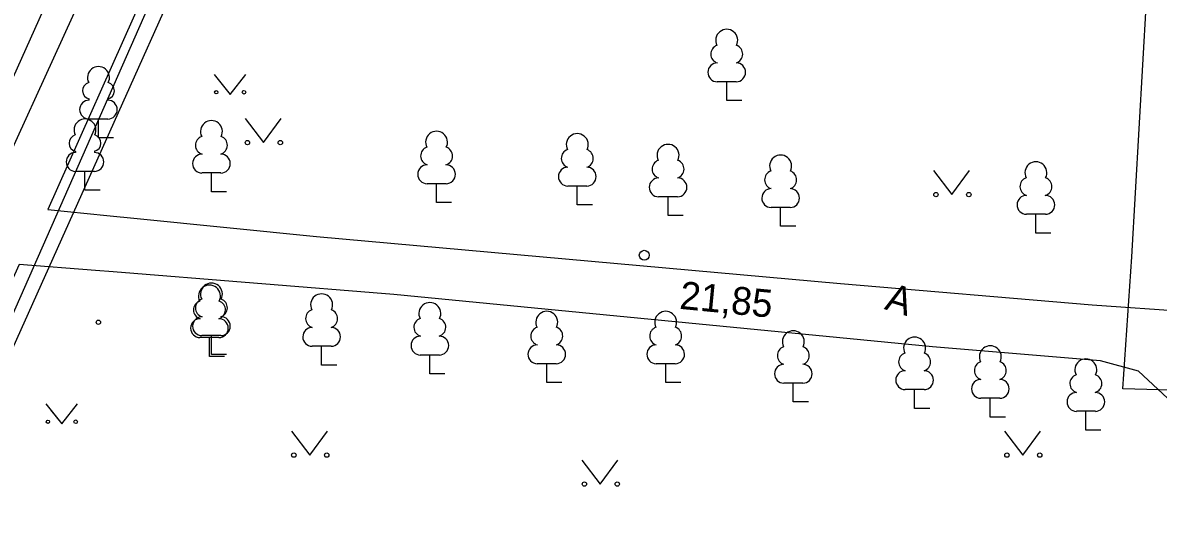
# Model space of a CAD drawing. Extents: x 714391 to 714584, y 6589993 to 6590151.
# Drawn here: x 714428.09 to 714456.74, y 6590018.98 to 6590031.55 of the extents above; entities that cross this region are included whole.
import ezdxf

# ---------------------------------------------------------------- set-up
doc = ezdxf.new("R2010")
doc.units = 0
for name, color, linetype in [('HALJASTUS', 7, 'Continuous'), ('HOONE', 7, 'Continuous'), ('KORGUS', 7, 'Continuous'), ('KPKAABEL', 7, 'Continuous'), ('PUU', 7, 'Continuous'), ('TEE', 7, 'Continuous'), ('По умолчанию', 7, 'Continuous'), ('Слой 1', 7, 'Continuous')]:
    doc.layers.add(name, color=color, linetype=linetype)

msp = doc.modelspace()

# ---------------------------------------------------------------- linework, layer by layer
at = {"layer": 'HALJASTUS'}
for p, q in [((714432.919, 6590030.25), (714433.324, 6590029.745)), ((714433.324, 6590029.745), (714433.719, 6590030.25)), ((714433.697, 6590029.137), (714434.16, 6590028.53)), ((714434.16, 6590028.53), (714434.606, 6590029.137)), ((714451.067, 6590027.827), (714451.53, 6590027.22)), ((714451.53, 6590027.22), (714451.976, 6590027.827)), ((714428.674, 6590021.941), (714429.079, 6590021.436)), ((714428.792, 6590021.794), (714429.079, 6590021.436)), ((714429.079, 6590021.436), (714429.474, 6590021.941)), ((714429.079, 6590021.436), (714429.474, 6590021.941)), ((714434.867, 6590021.257), (714435.33, 6590020.65)), ((714435.33, 6590020.65), (714435.776, 6590021.257)), ((714452.857, 6590021.257), (714453.32, 6590020.65)), ((714453.32, 6590020.65), (714453.766, 6590021.257)), ((714442.197, 6590020.527), (714442.66, 6590019.92)), ((714442.66, 6590019.92), (714443.106, 6590020.527))]:
    msp.add_line(p, q, dxfattribs=at)
for centre, radius in [((714432.971, 6590029.8), 0.0428), ((714433.671, 6590029.8), 0.0452), ((714433.759, 6590028.53), 0.055), ((714434.588, 6590028.53), 0.055), ((714451.129, 6590027.22), 0.055), ((714451.958, 6590027.22), 0.055), ((714428.726, 6590021.492), 0.0428), ((714428.726, 6590021.492), 0.0428), ((714429.426, 6590021.492), 0.0452), ((714429.426, 6590021.492), 0.0452), ((714434.929, 6590020.65), 0.055), ((714435.758, 6590020.65), 0.055), ((714452.919, 6590020.65), 0.055), ((714453.748, 6590020.65), 0.055), ((714442.259, 6590019.92), 0.055), ((714443.088, 6590019.92), 0.055)]:
    msp.add_circle(centre, radius, dxfattribs=at)
at = {"layer": 'HOONE'}
for points in [[(714459.73, 6590096.05), (714450.33, 6590074.44), (714440.46, 6590052.39), (714432.7, 6590035.24), (714421.56, 6590009.98), (714417.1, 6590000.12), (714413.783, 6589992.711)], [(714458.89, 6590022.24), (714455.84, 6590022.32), (714456.07, 6590025.65), (714456.9, 6590040.18), (714456.96, 6590042.47)]]:
    msp.add_lwpolyline(points, dxfattribs=at)
at = {"layer": 'KORGUS'}
msp.add_circle((714443.77, 6590025.69), 0.125, dxfattribs=at)
at = {"layer": 'KPKAABEL'}
msp.add_lwpolyline([(714390.649, 6590090.709), (714391.22, 6590087.72), (714411.651, 6590078.699), (714417.543, 6590076.021), (714419.18, 6590075.27), (714445.64, 6590069.88), (714433.16, 6590042.04), (714420.76, 6590014.4), (714410.92, 6589992.711)], dxfattribs=at)
at = {"layer": 'PUU'}
for p, q in [((714446.09, 6590030.065), (714445.61, 6590030.065)), ((714445.85, 6590029.59), (714445.85, 6590030.065)), ((714429.76, 6590029.63), (714429.76, 6590029.6)), ((714430.24, 6590029.63), (714430.24, 6590029.6)), ((714446.23, 6590029.59), (714445.85, 6590029.59)), ((714430.24, 6590029.125), (714429.76, 6590029.125)), ((714430, 6590028.65), (714430, 6590029.125)), ((714430.38, 6590028.65), (714430, 6590028.65)), ((714429.42, 6590028.31), (714429.42, 6590028.28)), ((714429.9, 6590028.31), (714429.9, 6590028.28)), ((714429.9, 6590027.805), (714429.42, 6590027.805)), ((714429.66, 6590027.33), (714429.66, 6590027.805)), ((714433.09, 6590027.765), (714432.61, 6590027.765)), ((714432.85, 6590027.29), (714432.85, 6590027.765)), ((714430.04, 6590027.33), (714429.66, 6590027.33)), ((714433.23, 6590027.29), (714432.85, 6590027.29)), ((714438.77, 6590027.495), (714438.29, 6590027.495)), ((714438.53, 6590027.02), (714438.53, 6590027.495)), ((714442.32, 6590027.435), (714441.84, 6590027.435)), ((714442.08, 6590026.96), (714442.08, 6590027.435)), ((714438.91, 6590027.02), (714438.53, 6590027.02)), ((714442.46, 6590026.96), (714442.08, 6590026.96)), ((714444.61, 6590027.165), (714444.13, 6590027.165)), ((714444.37, 6590026.69), (714444.37, 6590027.165)), ((714444.75, 6590026.69), (714444.37, 6590026.69)), ((714447.45, 6590026.895), (714446.97, 6590026.895)), ((714447.21, 6590026.42), (714447.21, 6590026.895)), ((714453.89, 6590026.725), (714453.41, 6590026.725)), ((714453.65, 6590026.25), (714453.65, 6590026.725)), ((714447.59, 6590026.42), (714447.21, 6590026.42)), ((714454.03, 6590026.25), (714453.65, 6590026.25)), ((714433.04, 6590023.615), (714432.56, 6590023.615)), ((714433.09, 6590023.665), (714432.61, 6590023.665)), ((714432.8, 6590023.14), (714432.8, 6590023.615)), ((714432.85, 6590023.19), (714432.85, 6590023.665)), ((714435.87, 6590023.395), (714435.39, 6590023.395)), ((714435.63, 6590022.92), (714435.63, 6590023.395)), ((714433.18, 6590023.14), (714432.8, 6590023.14)), ((714433.23, 6590023.19), (714432.85, 6590023.19)), ((714438.6, 6590023.175), (714438.12, 6590023.175)), ((714438.36, 6590022.7), (714438.36, 6590023.175)), ((714441.55, 6590022.955), (714441.07, 6590022.955)), ((714441.31, 6590022.48), (714441.31, 6590022.955)), ((714444.55, 6590022.955), (714444.07, 6590022.955)), ((714444.31, 6590022.48), (714444.31, 6590022.955)), ((714436.01, 6590022.92), (714435.63, 6590022.92)), ((714438.74, 6590022.7), (714438.36, 6590022.7)), ((714441.69, 6590022.48), (714441.31, 6590022.48)), ((714444.69, 6590022.48), (714444.31, 6590022.48)), ((714447.77, 6590022.465), (714447.29, 6590022.465)), ((714447.53, 6590021.99), (714447.53, 6590022.465)), ((714450.83, 6590022.305), (714450.35, 6590022.305)), ((714450.59, 6590021.83), (714450.59, 6590022.305)), ((714452.74, 6590022.085), (714452.26, 6590022.085)), ((714452.5, 6590021.61), (714452.5, 6590022.085)), ((714447.91, 6590021.99), (714447.53, 6590021.99)), ((714450.97, 6590021.83), (714450.59, 6590021.83)), ((714452.88, 6590021.61), (714452.5, 6590021.61)), ((714455.15, 6590021.755), (714454.67, 6590021.755)), ((714454.91, 6590021.28), (714454.91, 6590021.755)), ((714455.29, 6590021.28), (714454.91, 6590021.28))]:
    msp.add_line(p, q, dxfattribs=at)
for centre, radius, start, end in [((714445.85, 6590031.11), 0.277, 332.5799, 207.4201), ((714445.68, 6590030.763), 0.233, 109.0217, 253.1415), ((714446.02, 6590030.763), 0.233, 286.8508, 70.9859), ((714430, 6590030.17), 0.277, 332.5799, 207.4201), ((714445.613, 6590030.302), 0.238, 90.0016, 269.3953), ((714446.087, 6590030.302), 0.238, 270.6047, 89.9984), ((714429.81, 6590029.838), 0.212, 105.2441, 257.079), ((714430.19, 6590029.838), 0.212, 282.921, 74.7559), ((714429.762, 6590029.362), 0.237, 90, 270), ((714430.237, 6590029.362), 0.237, 270, 90), ((714429.66, 6590028.85), 0.277, 332.5799, 207.4201), ((714432.85, 6590028.81), 0.277, 332.5799, 207.4201), ((714429.47, 6590028.518), 0.212, 105.2441, 257.079), ((714429.85, 6590028.518), 0.212, 282.921, 74.7559), ((714432.68, 6590028.463), 0.233, 109.0217, 253.1415), ((714433.02, 6590028.463), 0.233, 286.8508, 70.9859), ((714438.53, 6590028.54), 0.277, 332.5799, 207.4201), ((714442.08, 6590028.48), 0.277, 332.5799, 207.4201), ((714438.36, 6590028.193), 0.233, 109.0217, 253.1415), ((714438.7, 6590028.193), 0.233, 286.8508, 70.9859), ((714444.37, 6590028.21), 0.277, 332.5799, 207.4201), ((714429.422, 6590028.043), 0.237, 90, 270), ((714429.897, 6590028.043), 0.237, 270, 90), ((714432.613, 6590028.002), 0.238, 90.0016, 269.3953), ((714433.087, 6590028.002), 0.238, 270.6047, 89.9984), ((714441.91, 6590028.133), 0.233, 109.0217, 253.1415), ((714442.25, 6590028.133), 0.233, 286.8508, 70.9859), ((714447.21, 6590027.94), 0.277, 332.5799, 207.4201), ((714438.293, 6590027.732), 0.238, 90.0016, 269.3953), ((714438.767, 6590027.732), 0.238, 270.6047, 89.9984), ((714441.843, 6590027.672), 0.238, 90.0016, 269.3953), ((714442.317, 6590027.672), 0.238, 270.6047, 89.9984), ((714444.2, 6590027.863), 0.233, 109.0217, 253.1415), ((714444.54, 6590027.863), 0.233, 286.8508, 70.9859), ((714447.04, 6590027.593), 0.233, 109.0217, 253.1415), ((714447.38, 6590027.593), 0.233, 286.8508, 70.9859), ((714453.65, 6590027.77), 0.277, 332.5799, 207.4201), ((714444.133, 6590027.402), 0.238, 90.0016, 269.3953), ((714444.607, 6590027.402), 0.238, 270.6047, 89.9984), ((714453.48, 6590027.423), 0.233, 109.0217, 253.1415), ((714453.82, 6590027.423), 0.233, 286.8508, 70.9859), ((714446.973, 6590027.132), 0.238, 90.0016, 269.3953), ((714447.447, 6590027.132), 0.238, 270.6047, 89.9984), ((714453.413, 6590026.962), 0.238, 90.0016, 269.3953), ((714453.887, 6590026.962), 0.238, 270.6047, 89.9984), ((714432.8, 6590024.66), 0.277, 332.5799, 207.4201), ((714432.85, 6590024.71), 0.277, 332.5799, 207.4201), ((714435.63, 6590024.44), 0.277, 332.5799, 207.4201), ((714432.63, 6590024.313), 0.233, 109.0217, 253.1415), ((714432.68, 6590024.363), 0.233, 109.0217, 253.1415), ((714432.97, 6590024.313), 0.233, 286.8508, 70.9859), ((714433.02, 6590024.363), 0.233, 286.8508, 70.9859), ((714438.36, 6590024.22), 0.277, 332.5799, 207.4201), ((714432.563, 6590023.852), 0.238, 90.0016, 269.3953), ((714432.613, 6590023.902), 0.238, 90.0016, 269.3953), ((714433.037, 6590023.852), 0.238, 270.6047, 89.9984), ((714433.087, 6590023.902), 0.238, 270.6047, 89.9984), ((714435.46, 6590024.093), 0.233, 109.0217, 253.1415), ((714435.8, 6590024.093), 0.233, 286.8508, 70.9859), ((714438.19, 6590023.873), 0.233, 109.0217, 253.1415), ((714438.53, 6590023.873), 0.233, 286.8508, 70.9859), ((714441.31, 6590024), 0.277, 332.5799, 207.4201), ((714444.31, 6590024), 0.277, 332.5799, 207.4201), ((714435.393, 6590023.632), 0.238, 90.0016, 269.3953), ((714435.867, 6590023.632), 0.238, 270.6047, 89.9984), ((714441.14, 6590023.653), 0.233, 109.0217, 253.1415), ((714441.48, 6590023.653), 0.233, 286.8508, 70.9859), ((714444.14, 6590023.653), 0.233, 109.0217, 253.1415), ((714444.48, 6590023.653), 0.233, 286.8508, 70.9859), ((714438.123, 6590023.412), 0.238, 90.0016, 269.3953), ((714438.597, 6590023.412), 0.238, 270.6047, 89.9984), ((714447.53, 6590023.51), 0.277, 332.5799, 207.4201), ((714450.59, 6590023.35), 0.277, 332.5799, 207.4201), ((714441.073, 6590023.192), 0.238, 90.0016, 269.3953), ((714441.547, 6590023.192), 0.238, 270.6047, 89.9984), ((714444.073, 6590023.192), 0.238, 90.0016, 269.3953), ((714444.547, 6590023.192), 0.238, 270.6047, 89.9984), ((714447.36, 6590023.163), 0.233, 109.0217, 253.1415), ((714447.7, 6590023.163), 0.233, 286.8508, 70.9859), ((714450.42, 6590023.003), 0.233, 109.0217, 253.1415), ((714450.76, 6590023.003), 0.233, 286.8508, 70.9859), ((714452.5, 6590023.13), 0.277, 332.5799, 207.4201), ((714447.293, 6590022.702), 0.238, 90.0016, 269.3953), ((714447.767, 6590022.702), 0.238, 270.6047, 89.9984), ((714452.33, 6590022.783), 0.233, 109.0217, 253.1415), ((714452.67, 6590022.783), 0.233, 286.8508, 70.9859), ((714454.91, 6590022.8), 0.277, 332.5799, 207.4201), ((714450.353, 6590022.542), 0.238, 90.0016, 269.3953), ((714450.827, 6590022.542), 0.238, 270.6047, 89.9984), ((714454.74, 6590022.453), 0.233, 109.0217, 253.1415), ((714455.08, 6590022.453), 0.233, 286.8508, 70.9859), ((714452.263, 6590022.322), 0.238, 90.0016, 269.3953), ((714452.737, 6590022.322), 0.238, 270.6047, 89.9984), ((714454.673, 6590021.992), 0.238, 90.0016, 269.3953), ((714455.147, 6590021.992), 0.238, 270.6047, 89.9984)]:
    msp.add_arc(centre, radius, start, end, dxfattribs=at)
at = {"layer": 'TEE'}
for points in [[(714430.249, 6590044.003), (714434.63, 6590043.29), (714427.02, 6590026.64), (714422.304, 6590026.966)], [(714458.41, 6590041.84), (714457.61, 6590042.45), (714451.01, 6590042.74), (714438.326, 6590043.121), (714437.835, 6590043.135), (714436.01, 6590043.19), (714428.72, 6590026.84), (714430.208, 6590026.691), (714430.977, 6590026.614), (714435.5, 6590026.16), (714448.72, 6590024.98), (714455.07, 6590024.44), (714457.48, 6590024.27)], [(714457.41, 6590021.74), (714456.97, 6590022.09), (714456.24, 6590022.77), (714455.28, 6590023.03), (714451.04, 6590023.38), (714437.45, 6590024.7), (714430.368, 6590025.27), (714429.927, 6590025.305), (714428, 6590025.46), (714417.4, 6590001.98), (714418.881, 6590001.433), (714419.464, 6590001.218), (714420.84, 6590000.71), (714421.59, 6590000.94), (714422.12, 6590001.13), (714422.82, 6590001)]]:
    msp.add_lwpolyline(points, dxfattribs=at)
at = {"layer": 'По умолчанию'}
msp.add_circle((714429.998, 6590024), 0.055, dxfattribs=at)
at = {"layer": 'Слой 1'}
msp.add_lwpolyline([(714455.78, 6590085.63), (714478.99, 6590085.97), (714478.28, 6590068.22), (714475.39, 6590009.54), (714423.1, 6590012.8)], close=True, dxfattribs=at)

# ---------------------------------------------------------------- texts
at = {"layer": 'KORGUS'}
msp.add_text('21,85', height=0.7, rotation=354.4446, dxfattribs=at).set_placement((714444.642, 6590024.341))
at = {"layer": 'TEE'}
msp.add_text('A', height=0.7, rotation=342.9376, dxfattribs=at).set_placement((714449.807, 6590024.336))

doc.saveas('drawing.dxf')
